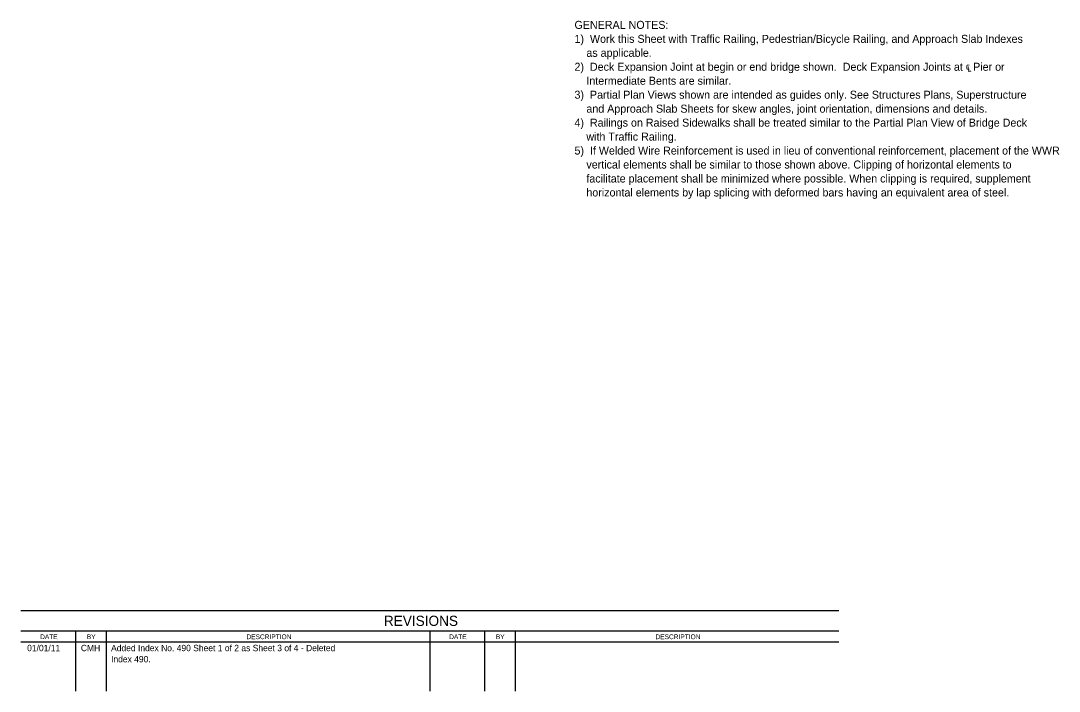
# Model space of a CAD drawing. Extents: x 122731 to 122840, y 88054 to 88118.
# Drawn here: x 122731.97 to 122771.22, y 88054.48 to 88079.83 of the extents above; entities that cross this region are included whole.
import ezdxf

# ---------------------------------------------------------------- set-up
doc = ezdxf.new("R2010")
doc.units = 0
for name, color, linetype in [('Border', 7, 'Continuous'), ('Dimension', 7, 'Continuous'), ('TextStructures', 7, 'Continuous')]:
    doc.layers.add(name, color=color, linetype=linetype)

msp = doc.modelspace()

# ---------------------------------------------------------------- linework, layer by layer
at = {"layer": 'Border'}
for p, q in [((122762.892, 88057.528), (122731.974, 88057.528)), ((122762.892, 88056.755), (122731.974, 88056.755)), ((122734.039, 88056.755), (122734.039, 88054.483)), ((122735.2, 88056.755), (122735.2, 88054.483)), ((122747.434, 88056.755), (122747.434, 88054.483)), ((122749.499, 88056.755), (122749.499, 88054.483)), ((122750.659, 88056.755), (122750.659, 88054.483)), ((122731.974, 88056.346), (122762.892, 88056.346))]:
    msp.add_line(p, q, dxfattribs=at)

# ---------------------------------------------------------------- texts
at = {"layer": 'Dimension'}
for s, height, p in [('GENERAL NOTES:', 0.3024, (122752.902, 88079.524)), ('1)  Work this Sheet with Traffic Railing, Pedestrian/Bicycle Railing, and Approach Slab Indexes ', 0.3024, (122752.902, 88078.996)), ('    as applicable.', 0.3024, (122752.902, 88078.468)), ('2)  Deck Expansion Joint at begin or end bridge shown.  Deck Expansion Joints at ℄ Pier or ', 0.3024, (122752.902, 88077.94)), ('    Intermediate Bents are similar.', 0.3024, (122752.902, 88077.412)), ('3)  Partial Plan Views shown are intended as guides only. See Structures Plans, Superstructure ', 0.3024, (122752.902, 88076.884)), ('    and Approach Slab Sheets for skew angles, joint orientation, dimensions and details. ', 0.3024, (122752.902, 88076.356)), ('4)  Railings on Raised Sidewalks shall be treated similar to the Partial Plan View of Bridge Deck ', 0.3024, (122752.902, 88075.828)), ('    with Traffic Railing.', 0.3024, (122752.902, 88075.3)), ('5)  If Welded Wire Reinforcement is used in lieu of conventional reinforcement, placement of the WWR ', 0.302401, (122752.902, 88074.772)), ('    vertical elements shall be similar to those shown above. Clipping of horizontal elements to ', 0.3024, (122752.902, 88074.244)), ('    facilitate placement shall be minimized where possible. When clipping is required, supplement', 0.3024, (122752.902, 88073.716)), ('    horizontal elements by lap splicing with deformed bars having an equivalent area of steel.', 0.3024, (122752.902, 88073.188))]:
    msp.add_text(s, height=height, dxfattribs=at).set_placement(p)
at = {"layer": 'TextStructures'}
for s, height, p in [('REVISIONS', 0.385, (122745.697, 88056.953)), ('BY', 0.1802, (122734.471, 88056.452)), ('BY', 0.1802, (122749.93, 88056.452)), ('01/01/11', 0.24, (122732.215, 88055.997)), ('CMH', 0.24, (122734.247, 88055.997)), ('Added Index No. 490 Sheet 1 of 2 as Sheet 3 of 4 - Deleted', 0.24, (122735.387, 88055.997)), ('Index 490.', 0.24, (122735.387, 88055.575))]:
    msp.add_text(s, height=height, dxfattribs=at).set_placement(p)
for s, height, rotation, p in [('DATE', 0.1794, 359.8693, (122732.707, 88056.453)), ('DESCRIPTION', 0.1801, 0.0498, (122740.504, 88056.451)), ('DATE', 0.1794, 359.8693, (122748.166, 88056.453)), ('DESCRIPTION', 0.1801, 0.0498, (122755.963, 88056.451))]:
    msp.add_text(s, height=height, rotation=rotation, dxfattribs=at).set_placement(p)

doc.saveas('drawing.dxf')
